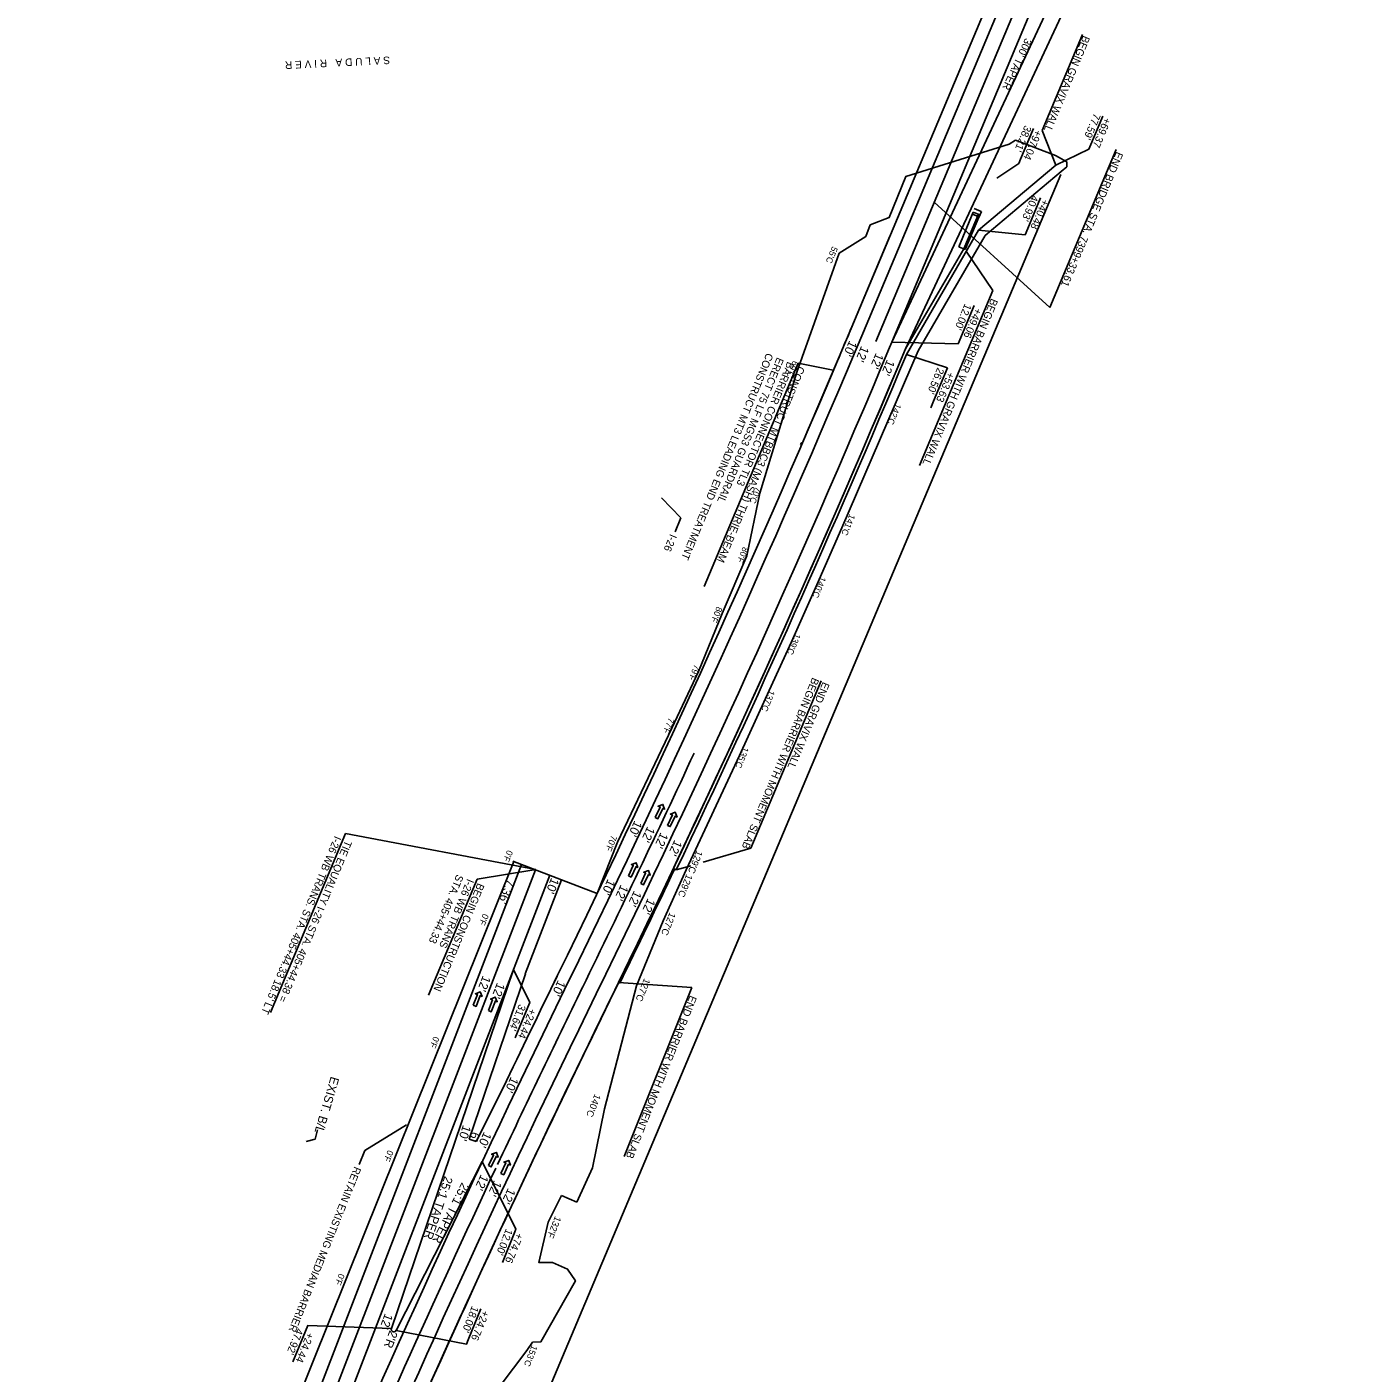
# Model space of a CAD drawing. Extents: x 1966090 to 1975830, y 788086 to 801233.
# Drawn here: x 1967920 to 1968973, y 795777 to 796844 of the extents above; entities that cross this region are included whole.
import ezdxf

# ---------------------------------------------------------------- set-up
doc = ezdxf.new("R2010")
doc.units = 0
for name, color, linetype in [('BR_PRESTRESSED BEAM', 7, 'Continuous'), ('BR_PROPOSED_DRAINAGE', 7, 'Continuous'), ('BR_REBAR', 7, 'Continuous'), ('BR_STRUCTURAL STEEL', 7, 'Continuous'), ('RD_EX_Driveway_txCode', 7, 'Continuous'), ('RD_EX_RW_TX', 7, 'Continuous'), ('RD_EX_SU_Gas', 7, 'Continuous'), ('RD_EX_SU_SwpLmt', 7, 'Continuous'), ('RD_EX_TX_Dam_ELEV', 7, 'Continuous'), ('RD_PD_PaveShd', 7, 'Continuous'), ('RD_Sketch6', 7, 'Continuous'), ('RD_Sketch8', 7, 'Continuous')]:
    doc.layers.add(name, color=color, linetype=linetype)

msp = doc.modelspace()

# ---------------------------------------------------------------- linework, layer by layer
at = {"layer": 'BR_PRESTRESSED BEAM'}
for p, q in [((1968572.3, 796603), (1968603.8, 796678.1)), ((1968562, 796578.7), (1968533.8, 796512.5)), ((1968532.9, 796512.9), (1968533.9, 796514.6)), ((1968533.8, 796512.5), (1968532.9, 796512.9)), ((1968534.6, 796514.3), (1968533.8, 796512.5)), ((1968533.9, 796514.6), (1968534.6, 796514.3))]:
    msp.add_line(p, q, dxfattribs=at)
for centre, radius, start, end in [((1959629, 800353.9), 9698, 337.09036, 337.27075), ((1977342.9, 791688), 9976, 153.83942, 155.84613)]:
    msp.add_arc(centre, radius, start, end, dxfattribs=at)
at = {"layer": 'BR_PROPOSED_DRAINAGE'}
for p, q in [((1968735, 796742.2), (1968703.3, 796754.2)), ((1968744.2, 796737.1), (1968735, 796742.2)), ((1968744.1, 796733.2), (1968744.2, 796737.1)), ((1968679.4, 796678.6), (1968739.5, 796729.4)), ((1968739.5, 796729.4), (1968744.1, 796733.2)), ((1968588.3, 796687.1), (1968584.8, 796677.8)), ((1968679.4, 796678.6), (1968626.3, 796587.3)), ((1968563.7, 796664.7), (1968530.1, 796570.4)), ((1968626.3, 796587.3), (1968565.8, 796446.9)), ((1968530.1, 796570.4), (1968500.7, 796474.3)), ((1968500.7, 796474.3), (1968490.3, 796424.6)), ((1968565.8, 796446.9), (1968545.8, 796401.6)), ((1968470.9, 796378.9), (1968490.3, 796424.6)), ((1968545.8, 796401.6), (1968525.7, 796356.4)), ((1968470.9, 796378.9), (1968452, 796333)), ((1968525.7, 796356.4), (1968505.3, 796311.4)), ((1968452, 796333), (1968430.9, 796288)), ((1968505.3, 796311.4), (1968484.7, 796266.3)), ((1968430.9, 796288), (1968387.8, 796197.5)), ((1968484.7, 796266.3), (1968442.2, 796175.6)), ((1968387.8, 796197.5), (1968371.8, 796156.9)), ((1968305.8, 796182.3), (1967919.7, 795221.1)), ((1968371.8, 796156.9), (1968305, 796182.6)), ((1968424.1, 796135.1), (1968442.2, 796175.6)), ((1968424.1, 796135.1), (1968402.9, 796083.7)), ((1968402.9, 796083.7), (1968377.5, 795986.1)), ((1968368, 795939.4), (1968377.5, 795986.1)), ((1968355.7, 795912.1), (1968368, 795939.4)), ((1968343.5, 795917.5), (1968332.9, 795896.2)), ((1968343.5, 795917.5), (1968355.7, 795912.1)), ((1968316.1, 795794.4), (1968253.8, 795712.1))]:
    msp.add_line(p, q, dxfattribs=at)
for points in [[(1968588.3, 796687.1), (1968603.3, 796693), (1968616.6, 796725.5), (1968698.3, 796751), (1968703.3, 796754.2)], [(1968584.8, 796677.8), (1968563.7, 796664.7)], [(1968332.9, 795896.2), (1968325.6, 795864.2), (1968336.5, 795864.3), (1968348.3, 795859.1), (1968354.5, 795849.8), (1968327.2, 795801.4), (1968320.6, 795801), (1968316.1, 795794.4)]]:
    msp.add_lwpolyline(points, dxfattribs=at)
at = {"layer": 'BR_REBAR'}
for p, q in [((1968735.4, 796734.4), (1968674.1, 796683)), ((1968674, 796695.5), (1968662.5, 796668)), ((1968674.1, 796683), (1968617, 796584.2)), ((1968616.2, 796588.8), (1968662.5, 796668)), ((1968434.5, 796175.6), (1968432.2, 796176.6)), ((1968388.8, 796086.3), (1968389.8, 796085.8))]:
    msp.add_line(p, q, dxfattribs=at)
for radius, start, end in [(9744, 333.93129, 337.26924), (9744, 334.02533, 337.26924), (9746.5, 334.61481, 337.24601), (9745.1, 334.02533, 334.6148)]:
    msp.add_arc((1959629, 800353.9), radius, start, end, dxfattribs=at)
at = {"layer": 'BR_STRUCTURAL STEEL'}
for p, q in [((1968669.9, 796697.2), (1968658.4, 796669.7)), ((1968675, 796695.1), (1968663.5, 796667.6)), ((1968669.2, 796695.7), (1968674.4, 796693.6)), ((1968669.8, 796697.2), (1968675.2, 796695)), ((1968670.6, 796700.1), (1968676.1, 796697.8)), ((1968674.4, 796693.6), (1968674.6, 796693.5)), ((1968676.4, 796697.7), (1968674.6, 796693.5)), ((1968676.1, 796697.8), (1968676.4, 796697.7)), ((1968658.4, 796669.7), (1968663.5, 796667.6))]:
    msp.add_line(p, q, dxfattribs=at)
at = {"layer": 'RD_EX_Driveway_txCode'}
for points in [[(1968417.7, 796217.1), (1968419.9, 796216.1), (1968423.8, 796224.4), (1968425.2, 796223.7), (1968423.9, 796227.5), (1968420.1, 796226.1), (1968421.6, 796225.4)], [(1968427.5, 796210.9), (1968429.7, 796209.9), (1968433.6, 796218.2), (1968435.1, 796217.5), (1968433.7, 796221.3), (1968429.9, 796219.9), (1968431.4, 796219.2)], [(1968396.5, 796170.9), (1968398.7, 796169.9), (1968402.6, 796178.2), (1968404, 796177.5), (1968402.7, 796181.3), (1968398.9, 796179.9), (1968400.4, 796179.2)], [(1968406.3, 796164.7), (1968408.5, 796163.7), (1968412.4, 796172), (1968413.9, 796171.3), (1968412.5, 796175), (1968408.7, 796173.7), (1968410.2, 796173)], [(1968273.5, 796068.2), (1968275.8, 796067.4), (1968279.1, 796075.9), (1968280.6, 796075.3), (1968279, 796079), (1968275.3, 796077.4), (1968276.8, 796076.8)], [(1968285.6, 796064), (1968287.8, 796063.1), (1968291.1, 796071.7), (1968292.6, 796071.1), (1968291, 796074.7), (1968287.3, 796073.1), (1968288.8, 796072.5)], [(1968285.7, 795941.1), (1968287.8, 795940.1), (1968291.7, 795948.4), (1968293.2, 795947.7), (1968291.9, 795951.5), (1968288.1, 795950.1), (1968289.6, 795949.4)], [(1968295.5, 795934.9), (1968297.7, 795933.8), (1968301.6, 795942.2), (1968303, 795941.5), (1968301.7, 795945.2), (1968297.9, 795943.9), (1968299.4, 795943.2)]]:
    msp.add_lwpolyline(points, close=True, dxfattribs=at)
at = {"layer": 'RD_EX_SU_Gas'}
for p, q in [((1968592.6, 796594.5), (1968973.4, 797502.5)), ((1968721.4, 796870.7), (1968605.4, 796594)), ((1968159.3, 795750.5), (1968323, 796175.7))]:
    msp.add_line(p, q, dxfattribs=at)
for centre, radius, start, end in [((1959629, 800353.9), 9720, 333.93129, 335.14309), ((1977342.9, 791688), 10000, 153.93129, 154.82338), ((1977342.9, 791688), 10000, 154.84327, 156.82865)]:
    msp.add_arc(centre, radius, start, end, dxfattribs=at)
at = {"layer": 'RD_EX_TX_Dam_ELEV'}
msp.add_line((1968739.3, 796727.1), (1968196.7, 795439.3), dxfattribs=at)
at = {"layer": 'RD_PD_PaveShd'}
for p, q in [((1968940.8, 797481.5), (1968572.3, 796603)), ((1968616.2, 796588.8), (1968743.5, 796861.2)), ((1968314.8, 796093.1), (1968343.6, 796167.8)), ((1968305.4, 796096.5), (1968208.7, 795812)), ((1968314.9, 796093.3), (1968270.3, 795962.1)), ((1968275.9, 795960.1), (1968297.3, 796002.9)), ((1968270.3, 795962.1), (1968275.9, 795960.1)), ((1968280.7, 795944.4), (1968212.4, 795810.4))]:
    msp.add_line(p, q, dxfattribs=at)
for centre, radius, start, end in [((1959629, 800353.9), 9698, 333.93129, 337.27075), ((1959629, 800353.9), 9744, 333.93129, 337.26924), ((1977342.9, 791688), 10022, 153.93129, 154.49907), ((1977342.9, 791688), 10022, 153.93129, 154.01192), ((1977342.9, 791688), 9976, 153.93129, 156.82865), ((1968210.5, 795811.2), 2, 154.62, 338.9299)]:
    msp.add_arc(centre, radius, start, end, dxfattribs=at)
at = {"layer": 'RD_Sketch6'}
for p, q in [((1968724.5, 796762), (1968756.4, 796838)), ((1968762.4, 796749), (1968772.6, 796773.2)), ((1968707.5, 796739.3), (1968717.7, 796763.6)), ((1968724.5, 796762), (1968735.4, 796734.4)), ((1968730.7, 796621.6), (1968783.3, 796746.8)), ((1968730.7, 796621.6), (1968639, 796705.1)), ((1968713.1, 796684.2), (1968723.3, 796708.5)), ((1968711, 796679.1), (1968674.1, 796683)), ((1968713.1, 796684.2), (1968711, 796679.1)), ((1968664.4, 796666.3), (1968685.5, 796635.1)), ((1968685.5, 796635.1), (1968627.3, 796496.3)), ((1968658, 796592.7), (1968670.7, 796623.1)), ((1968456.7, 796400.4), (1968531, 796577.5)), ((1968558.9, 796571.8), (1968531, 796577.5)), ((1968649.5, 796573.7), (1968617, 796584.2)), ((1968638.4, 796547.2), (1968649.5, 796573.7)), ((1968638.4, 796547.2), (1968636.2, 796542.1)), ((1968438.2, 796454.7), (1968422.7, 796470.6)), ((1968433.5, 796443.6), (1968438.2, 796454.7)), ((1968493.7, 796192.7), (1968549.4, 796325.6)), ((1968112.9, 796062.4), (1968172.4, 796204.4)), ((1968323.1, 796175.8), (1968172.4, 796204.4)), ((1968493.7, 796192.7), (1968455.9, 796181.8)), ((1968323.1, 796175.8), (1968276.7, 796168.3)), ((1968446, 796178.9), (1968434.5, 796175.6)), ((1968238.2, 796076.3), (1968276.7, 796168.3)), ((1968388.8, 796086.3), (1968446.9, 796082.3)), ((1968393.1, 795948.3), (1968446.9, 796082.3)), ((1968306.9, 796042.3), (1968316.8, 796066.7)), ((1968220.5, 795973.5), (1968187.5, 795953)), ((1968183, 795941.9), (1968187.5, 795953)), ((1968296.7, 795864.3), (1968306.5, 795888.7)), ((1968269.6, 795802.9), (1968279.5, 795827.4)), ((1968130.6, 795785.4), (1968140.5, 795809.9))]:
    msp.add_line(p, q, dxfattribs=at)
for points in [[(1968762.4, 796749), (1968761.6, 796747.1), (1968735.4, 796734.4)], [(1968707.5, 796739.3), (1968706.1, 796735.9), (1968688.6, 796724.2)], [(1968605.4, 796594), (1968658, 796592.7)], [(1968316.8, 796066.7), (1968318.3, 796070.5), (1968305.4, 796096.5)], [(1968150.2, 795969.4), (1968148.2, 795962.1), (1968141.1, 795960.3)], [(1968306.5, 795888.7), (1968307.3, 795890.6), (1968280.7, 795944.4)], [(1968140.5, 795809.9), (1968142.3, 795814.2), (1968208.7, 795812)], [(1968269.6, 795802.9), (1968268.3, 795799.6), (1968212.4, 795810.4)]]:
    msp.add_lwpolyline(points, dxfattribs=at)
at = {"layer": 'RD_Sketch8'}
for p, q in [((1968953.2, 797485.5), (1968581.5, 796599.1)), ((1968605.4, 796594), (1968732.5, 796866)), ((1968605.4, 796594), (1968603.6, 796589.8)), ((1968148.1, 795754.8), (1968311.8, 796180)), ((1968305, 796182.6), (1968371.8, 796156.9)), ((1968170.5, 795746.2), (1968334.2, 796171.4))]:
    msp.add_line(p, q, dxfattribs=at)
for centre, radius, start, end in [((1959629, 800353.9), 9708, 333.93129, 337.27075), ((1959629, 800353.9), 9732, 333.93129, 337.24601), ((1977342.9, 791688), 10012, 153.93129, 156.82865), ((1977342.9, 791688), 9988, 153.93129, 156.82865)]:
    msp.add_arc(centre, radius, start, end, dxfattribs=at)

# ---------------------------------------------------------------- texts
at = {"layer": 'RD_EX_Driveway_txCode'}
for s, rotation, p in [("10'", 244.8602, (1968571.9, 796595.9)), ("12'", 247.246, (1968581.2, 796591.5)), ("12'", 247.246, (1968592.8, 796586)), ("12'", 247.2476, (1968601.6, 796580.7)), ("10'", 244.8602, (1968401.5, 796215.1)), ("12'", 244.8586, (1968411.7, 796210.5)), ("12'", 244.8586, (1968422.2, 796205.8)), ("12'", 244.8586, (1968433.2, 796199.8)), ("7.36'", 248.9372, (1968300.4, 796168.9)), ("10'", 247.8752, (1968335.5, 796169.8)), ("10'", 244.8602, (1968380.3, 796168.8)), ("12'", 244.8586, (1968390.6, 796164.3)), ("12'", 244.8586, (1968401.1, 796159.6)), ("12'", 244.8586, (1968412, 796153.5)), ("12'", 248.9372, (1968281.2, 796092.2)), ("12'", 248.9372, (1968292.5, 796086.6)), ("10'", 244.8602, (1968340.8, 796088.6)), ("10'", 244.8586, (1968303.5, 796012)), ("10'", 251.1559, (1968265.5, 795973.7)), ("6'", 251.1559, (1968272.4, 795968.4)), ("10'", 244.8586, (1968282.2, 795968.4)), ('25:1 TAPER', 251.1962, (1968250.9, 795933.2)), ('25:1 TAPER', 243.0695, (1968264.5, 795928.1)), ("12'", 244.8586, (1968279.7, 795934.5)), ("12'", 244.8586, (1968290.2, 795929.8)), ("12'", 244.8586, (1968301.2, 795923.7)), ("12'", 249.6613, (1968203.6, 795824.3)), ("2'R", 249.6613, (1968207.3, 795810.8))]:
    msp.add_text(s, height=7, rotation=rotation, dxfattribs=at).set_placement(p)
at = {"layer": 'RD_EX_RW_TX'}
for s, rotation, p in [("55'C", 247.246, (1968558.1, 796670.4)), ("60'C", 247.246, (1968527, 796579.8)), ("142'C", 247.246, (1968608.4, 796545.9)), ("70'C", 247.246, (1968497.6, 796479.9)), ("141'C", 247.246, (1968571.9, 796458.1)), ("80'F", 247.246, (1968487.4, 796432.1)), ("140'C", 247.4117, (1968548.8, 796408.6)), ("80'F", 247.246, (1968466.7, 796384.8)), ("139'C", 247.6617, (1968528.6, 796363.5)), ("79'F", 247.246, (1968449, 796338.9)), ("137'C", 247.9117, (1968508.2, 796318.5)), ("77'F", 247.246, (1968428.6, 796296.7)), ("135'C", 248.119, (1968487.5, 796273.5)), ("70'F", 247.246, (1968383.1, 796203.5)), ("0'F", 247.246, (1968300.6, 796191.7)), ("0'F", 247.246, (1968281.4, 796141.3)), ("0'F", 247.246, (1968242.3, 796044)), ("0'F", 247.246, (1968205.9, 795953.8)), ("0'F", 247.246, (1968167.2, 795856)), ("153'C", 248.119, (1968320, 795799.1))]:
    msp.add_text(s, height=5, rotation=rotation, dxfattribs=at).set_placement(p)
at = {"layer": 'RD_EX_SU_SwpLmt'}
for s, p in [("129'C", (1968450.6, 796191.4)), ("129'C", (1968442.6, 796172.6)), ("127'C", (1968429.3, 796142.3)), ("127'C", (1968409.1, 796090)), ("140'C", (1968369.9, 795998.3)), ("132'F", (1968338.5, 795901.4))]:
    msp.add_text(s, height=5.4, rotation=248.119, dxfattribs=at).set_placement(p)
at = {"layer": 'RD_Sketch6'}
for s, height, rotation, p in [("300' TAPER", 6, 245.1667, (1968711.2, 796835.6)), ('BEGIN GRAVIX WALL', 6, 247.4058, (1968757.1, 796837.7)), ('S A L U D A   R I V E R', 6, 182.7896, (1968207.4, 796820.7)), ("77.59'", 6, 247.246, (1968765.6, 796776.1)), ('+69.37', 6, 247.246, (1968773.9, 796772.7)), ("38.21'", 6, 247.246, (1968710.8, 796766.5)), ('+97.04', 6, 247.246, (1968719.1, 796763)), ('END BRIDGE STA. 7399+33.61', 6, 247.4058, (1968783.4, 796745.6)), ("40.93'", 6, 247.246, (1968716.4, 796711.4)), ('+40.48', 6, 247.246, (1968724.7, 796707.9)), ('BEGIN BARRIER WITH GRAVIX WALL', 6, 247.4058, (1968684.2, 796629.2)), ("12.00'", 6, 247.246, (1968663.3, 796625.1)), ('+49.06', 6, 247.246, (1968671.6, 796621.6)), ('CONSTRUCT MT3 LEADING END TREATMENT', 6, 247.4058, (1968506.1, 796586)), ('ERECT 75 LF MGS3 GUARDRAIL', 6, 247.4058, (1968514.4, 796582.5)), ('BARRIER CONNECTOR TL3', 6, 247.4058, (1968522.7, 796579.1)), ('CONSTRUCT MTBBC3 (MASH) THRIE-BEAM', 6, 247.4058, (1968531, 796575.6)), ("26.50'", 6, 247.246, (1968641.6, 796574.4)), ('+53.63', 6, 247.246, (1968649.9, 796570.9)), ('I-26', 6, 247.246, (1968429.7, 796442.4)), ('BEGIN BARRIER WITH MOMENT SLAB', 6, 247.4058, (1968542.4, 796328.6)), ('END GRAVIX WALL ', 6, 247.4058, (1968550.7, 796325.1)), ("I-26 WB TRANS. STA. 405+44.33 18.5' LT", 6, 247.4075, (1968163.7, 796203)), ('TIE EQUALITY I-26 STA. 405+44.38 =', 6, 247.4075, (1968172, 796199.5)), ('STA. 405+44.33', 6, 247.4075, (1968260.5, 796172.5)), ('BEGIN CONSTRUCTION', 6, 247.4075, (1968277.1, 796165.6)), ('I-26 WB TRANS', 6, 247.4075, (1968268.8, 796169)), ('END BARRIER WITH MOMENT SLAB', 6, 248.3081, (1968445.4, 796076.5)), ("31.64'", 6, 248.0013, (1968309.9, 796069.5)), ('+24.44', 6, 248.0013, (1968318.2, 796066.2)), ('EXIST. B/L', 7, 253.6052, (1968160.7, 796012.2)), ('RETAIN EXISTING MEDIAN BARRIER', 6, 248.119, (1968179.3, 795940.8)), ("12.00'", 6, 248.0013, (1968299.6, 795891.5)), ('+74.76', 6, 248.0013, (1968307.9, 795888.2)), ("18.00'", 6, 248.0013, (1968272.6, 795830.2)), ('+24.76', 6, 248.0013, (1968280.9, 795826.8)), ("47.92'", 6, 248.0013, (1968133.5, 795812.7)), ('+24.44', 6, 248.0013, (1968141.9, 795809.3))]:
    msp.add_text(s, height=height, rotation=rotation, dxfattribs=at).set_placement(p)

doc.saveas('drawing.dxf')
